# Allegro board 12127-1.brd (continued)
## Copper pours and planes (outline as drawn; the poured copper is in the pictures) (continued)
GND on TOP: 128.5,54.81 128.32,54.99 128.32,60.99 128.45,61.11 132.26,61.11 133.27,60.1 133.27,55.4 132.69,54.81 ; 2 cut-outs
GND on TOP: 118.85,151.44 118.72,151.57 118.72,153.22 118.85,153.35 120.24,153.35 120.37,153.22 120.37,151.57 120.24,151.44
GND on TOP: 186.56,178.59 186.31,178.84 185.37,178.84 185.12,179.1 185.12,180.11 185.37,180.37 185.75,180.37 186.21,179.91 186.21,179.6 186.41,179.4 188.37,179.4 188.44,179.32 188.44,178.69 188.34,178.59
GND on TOP: 180.26,173 180.16,173.1 180.16,176.35 180.21,176.4 181.89,176.4 182.27,176.78 182.27,178.08 181.28,179.07 181.28,179.86 180.16,180.97 180.16,184.63 180.26,184.73 183.85,184.73 184.28,184.3 184.28,173.35 183.92,173 ; 2 cut-outs
GND on TOP: 88.37,202.84 87,204.22 87,205.61 87.86,206.48 90.75,206.48 90.93,206.3 90.93,203.1 90.68,202.84
GND on TOP: 113.94,208.18 113.79,208.33 113.79,209.25 114,209.45 117.5,209.45 117.58,209.37 117.58,208.25 117.5,208.18
GND on BOTTOM: 14.43,3.87 14.73,4.18 14.73,5.08 12.83,6.99 12.83,8 12.06,8.76 11.43,8.76 10.79,8.13 10.79,6.86 9.73,5.79 9.73,5.21 10.39,4.55 11.48,4.55 12.15,3.87
GND on BOTTOM: 128.45,61.11 132.26,61.11 133.27,60.1 133.27,55.4 132.69,54.81 128.5,54.81 128.32,54.99 128.32,60.99
GND on BOTTOM: 154.31,80.64 154.56,80.39 154.56,76.96 152.48,74.88 137.38,74.88 136.1,76.16 136.1,80.05 136.7,80.64
GND on BOTTOM: 87.88,64.9 86.87,63.88 82.8,63.88 71.27,75.41 71.27,79.76 72.03,80.52 86.23,80.52 87.88,78.87
GND on BOTTOM: 106.68,78.61 106.68,73.79 105.66,72.77 105.66,72.39 105.92,72.14 108.08,72.14 108.33,71.88 108.33,68.96 107.95,68.58 92.48,68.58 91.44,69.62 91.44,76 94.36,78.92 106.38,78.92
GND on BOTTOM: 63.88,242.7 63.88,230.5 64.14,230.25 64.9,230.25 70.36,235.71 79.12,235.71 79.76,236.35 79.76,242.7 79.25,243.21 64.39,243.21
GND on BOTTOM: 94.92,147.63 103.86,147.63 104.11,147.38 104.11,147.32 104.78,146.66 104.78,144.91 106.17,143.51 106.99,143.51 107.41,143.09 114.62,143.09 115.92,141.79 115.92,140.65 116.18,140.39 117.7,140.39 117.83,140.52 117.83,141.79 118.08,142.04 126.34,142.04 127.35,143.06 127.35,145.83 129.03,147.51 132.18,147.51 132.56,147.12 133.58,147.12 134.34,147.89 135.19,147.89 138.23,150.93 149.45,150.93 169.54,130.84 169.54,122.46 176.04,115.97 176.04,86.96 174.71,85.64 160.39,85.64 160.1,85.34 58.93,85.34 57.66,86.61 57.66,87.76 55.89,89.52 54.85,89.52 53.63,90.74 53.63,92.85 51.69,94.79 51.69,100.66 51.66,100.69 51.66,100.97 51.03,101.6 50.29,101.6 49.91,101.22 49.91,86.49 49.78,86.36 47.77,86.36 47.65,86.49 47.65,105.05 51.44,108.84 51.44,113.7 81.81,144.08 82.52,144.08 86.6,148.15 94.4,148.15
GND on BOTTOM: outline of 119 points within 61.59,0.76 199.21,243.21
GND on BOTTOM: 15.95,236.3 16.54,235.71 19.56,235.71 19.81,235.46 19.81,229.36 15.75,225.3 10.67,225.3 10.31,225.65 10.31,228.75 9.45,229.62 9.45,232.16 9.91,232.61 14.15,232.61 14.48,232.28 14.48,227.33 14.99,226.82 15.49,226.82 17.02,228.35 17.02,234.57 16.64,234.95 15.62,234.95 14.61,233.93 3.02,233.93 0.76,231.67 0.76,242.94 0.77,242.94 0.77,243.02 0.96,243.21 15.74,243.21 15.95,243
GND on L2VCC: 31.78,6.93 40.58,6.51 31.78,6.09
GND on L2VCC: 18.62,22.42 18.22,22.81 18.22,25.7 19.89,27.37 20.91,27.37 22.42,28.88 22.42,30.02 24.45,32.05 24.45,32.81 27.24,35.61 27.24,37.51 27.38,37.66 27.73,37.66 27.88,37.51 27.88,34.5 25.34,31.96 25.34,31.07 23.43,29.16 23.43,23.95 21.89,22.42
GND on L2VCC: outline of 272 points within 0.76,0.76 199.24,243.24 ; 113 cut-outs
GND on L2VCC: 46.13,0.76 46.13,1.59 45.66,2.06 37.95,2.06 40.64,4.77 40.49,8.59 40.71,8.62 40.88,8.76 48.18,1.46 181.43,1.46 197.68,17.7 197.68,30.29 199.24,30.29 199.24,1 199.17,0.83 199,0.76 ; 1 cut-out
GND on L2VCC: 193.65,83.33 193.65,74.47
GND on L2VCC: 193.65,10.94 193.65,2.08
GND on L3: 1,0.76 0.83,0.83 0.76,1 0.76,243 0.83,243.17 1,243.24 15.88,243.24 15.88,236.24 16.53,235.59 19.45,235.59 19.81,235.23 19.81,229.59 15.64,225.43 10.13,225.43 9.14,226.42 9.14,228.17 6.93,230.38 3.66,230.38 2.92,229.64 2.92,203.22 4.47,201.68 6.96,201.68 7.49,202.21 7.49,203.22 7.73,203.45 10.65,203.45 13.59,206.4 13.59,208.3 15.22,209.93 17.12,209.93 20.93,213.74 47.07,213.74 57.86,224.54 59.16,224.54 63.75,229.13 63.75,243.24 199,243.24 199.17,243.17 199.24,243 199.24,1 199.17,0.83 199,0.76 45.72,0.76 45.62,0.86 45.62,1.91 45.19,2.34 29.03,2.34 28.78,2.08 28.78,0.92 28.63,0.76 ; 128 cut-outs
VBAT2 on L2VCC: 99.77,40.32 93.17,46.93 85.63,46.93 85.38,47.17 85.38,47.97 85.56,48.15 93.6,48.15 100.84,40.91 142.78,40.91 143.41,41.54 145.79,41.54 146.04,41.3 146.04,40.32
VCC on TOP: 187.58,21.34 184.66,24.26 184.66,27.36 186.94,29.64 190.7,29.64 191.13,29.21 191.13,21.97 190.5,21.34 ; 2 cut-outs
VCC on TOP: 170.56,51.56 170.05,52.07 170.05,54.61 170.54,55.09 173.61,55.09 174.02,54.69 174.02,52.22 173.35,51.56
VCC on TOP: 118.36,215.52 117.98,215.9 117.98,218.19 118.36,218.57 118.36,220.85 118.62,221.11 120.4,221.11 120.65,220.85 120.65,218.31 120.02,217.68 120.02,215.9 119.63,215.52 ; 2 cut-outs
VCC on TOP: 189.74,196.9 189.36,197.28 189.36,199.19 189.51,199.34 194.31,199.34 194.87,198.78 194.87,197.28 194.49,196.9
VCC on TOP: 186.79,38.68 184.47,41 181.3,41 180.31,41.99 176.56,41.99 175.87,42.67 175.87,46.51 176.1,46.74 179.15,46.74 180.34,47.93 195.78,47.93 196.09,47.62 196.09,39.12 195.66,38.68
VCC on BOTTOM: 174.37,44.07 174.37,53.34 173.99,53.72 170.31,53.72 169.42,52.83 169.42,43.81 169.93,43.31 173.61,43.31
VCC on BOTTOM: 192.53,42.8 195.83,42.8 196.47,43.43 196.47,68.58 194.31,70.74 192.02,70.74 191.64,70.36 191.64,43.69
VCC on L2VCC: 183.2,22.54 183.2,35.51 182.32,36.39 167.08,36.39 167.02,36.45 167.02,40.21 165.31,41.92 161.29,41.92 155.99,47.22 155.99,49.43 156.92,50.36 166.61,50.36 166.7,50.37 166.77,50.42 171.55,55.16 177.7,55.16 178.63,56.08 178.63,65.25 179.15,65.77 183.21,65.77 183.83,66.39 183.83,87.04 189.93,93.14 189.93,108.38 191.2,109.65 191.2,116 193.36,118.16 193.36,186.01 191.45,187.91 191.45,196.17 190.58,197.04 190.56,197.04 190.56,200.47 199.24,200.47 199.24,30.67 191.95,30.67 190.44,29.16 190.44,23.45 189.53,22.54 ; 1 cut-out
VCC3 on TOP: 10.16,37.72 9.02,38.86 9.02,41.4 9.14,41.53 9.53,41.53 9.78,41.27 9.78,40.01 9.91,39.88 13.08,39.88 13.34,39.62 13.34,39.24 13.08,38.99 11.43,38.99 11.18,38.73 11.18,37.85 11.05,37.72 ; 2 cut-outs
VCC3 on TOP: outline of 128 points within 12.42,51.41 31.11,67.06 ; 11 cut-outs
VCC3 on TOP: 20.14,188.21 18.97,189.38 17.58,189.38 17.37,189.59 17.37,191.29 17.65,191.57 19.33,191.57 20.14,190.75 20.9,190.75 24.08,193.93 24.08,193.94 24.9,194.76 29.09,194.76 30.86,192.99 32.92,192.99 33.46,192.44 35.75,192.44 35.89,192.3 36.14,192.3 36.3,192.15 38.4,192.15 38.79,191.77 39.75,191.77 40.64,190.88 43.05,190.88 43.31,190.63 43.31,188.85 42.93,188.47 40.64,188.47 39.5,189.61 38.25,189.61 38.24,189.62 37.88,189.62 36.45,191.06 33.3,191.06 31.6,189.36 26.67,189.36 26.65,189.38 25.76,189.38 25.02,188.63 21.83,188.63 21.41,188.21 ; 8 cut-outs
VCC3 on TOP: 100.08,37.74 99.75,38.07 99.75,41.53 105.59,47.37 105.59,51 105.38,51.21 102.51,51.21 101.96,51.77 98.15,51.77 98.06,51.85 98.06,52.31 98.12,52.37 102.23,52.37 102.59,52.02 103.07,52.02 103.43,52.37 106.38,52.37 106.88,51.87 106.88,46.79 101.09,41 101.09,38.02 100.81,37.74 ; 2 cut-outs
VCC3 on TOP: 47.9,22.53 46.99,23.44 47.02,23.44 47.02,24.74 47.07,24.79 47.96,24.79 48.9,23.85 50.04,23.85 50.29,23.6 50.29,22.73 50.09,22.53
VCC3 on TOP: 69.24,73 68.12,74.12 61.09,74.12 60.96,74.24 60.96,75.26 61.21,75.51 70.18,75.51 70.51,75.18 70.51,73.25 70.26,73
VCC3 on TOP: 110.24,8.51 110.11,8.64 110.11,11.68 110.24,11.81 110.87,11.81 111.12,12.06 111.63,12.06 111.89,11.81 111.89,9.02 111.38,8.51 ; 1 cut-out
VCC3 on TOP: 55.37,85.09 53.72,86.74 53.72,87.38 53.98,87.63 53.98,89.66 54.74,90.42 54.74,91.19 53.72,92.2 53.72,93.47 54.74,94.49 54.74,95.38 54.23,95.89 54.23,96.77 54.61,97.16 55.5,97.16 57.28,95.38 57.28,90.55 57.66,90.17 57.66,85.47 57.28,85.09
VCC3 on TOP: 15.8,233.17 15.16,233.81 14.1,233.81 13.94,233.96 13.94,235.59 13.59,235.94 13.59,236.58 13.79,236.78 16,236.78 16.84,235.94 17.68,235.94 17.86,235.76 17.86,233.43 17.6,233.17 ; 1 cut-out
VCC3 on TOP: 15.01,40.01 14.33,40.69 14.33,41.83 13.74,42.42 13.74,44.04 11.73,46.05 11.73,47.19 11.81,47.27 12.17,47.27 12.73,47.83 13.41,47.83 13.94,48.36 15.8,48.36 15.88,48.29 15.88,47.83 15.7,47.65 14.22,47.65 14.07,47.5 14.07,44.58 14.55,44.09 15.75,44.09 15.85,43.99 15.85,42.75 15.49,42.39 15.49,40.77 15.34,40.61 15.34,40.13 15.21,40.01 ; 5 cut-outs
VCC3 on TOP: 182.25,59.31 181.23,60.33 181.23,67.56 182.25,68.58 194.82,68.58 195.83,67.56 195.83,60.33 194.82,59.31 ; 2 cut-outs
VCC3 on TOP: 75.82,59.44 74.17,61.09 63.73,61.09 63.22,61.59 63.22,66.34 63.3,66.42 65.91,66.42 66.04,66.29 66.04,63.37 66.29,63.12 76.58,63.12 77.47,62.23 77.47,61.47 78.74,60.2 78.74,59.69 78.49,59.44 ; 4 cut-outs
VCC3 on BOTTOM: 79.2,57.73 79.2,46.43 79.18,46.42 79.18,45.66 78.49,44.96 77.22,44.96 76.48,45.69 76.48,66.4 69.27,73.61 69.27,75.49 69.41,75.63 70.04,75.63 81.15,64.52 81.15,59.69
VCC3 on BOTTOM: 54.86,80.52 54.86,85.47 55.37,85.98 57.28,85.98 57.53,85.72 57.53,82.93 59.31,81.15 60.83,81.15 63.37,78.61 63.37,75.18 62.48,74.3 61.09,74.3
VCC3 on BOTTOM: 186.69,45.47 185.93,44.7 185.93,28.96 184.91,27.94 184.91,23.75 185.8,22.86 195.58,22.86 196.34,22.1 196.34,17.02 195.2,15.88 181.36,15.88 176.96,20.27 176.96,30.38 177.1,30.52 177.1,40.09 178.71,41.71 178.71,46.2 180.59,48.08 180.59,62.31 186.99,68.71 190.02,68.71 190.37,68.35 190.37,59.69 189.99,59.31 187.83,59.31 186.69,58.17
VCC3 on L2VCC: outline of 143 points within 6.54,13.4 182.82,197.68 ; 1 cut-out
VCC3_3SBREF on TOP: 173.99,20.19 173.48,20.7 173.48,23.24 173.74,23.5 177.16,23.5 177.29,23.37 177.29,21.21 177.04,20.95 176.4,20.95 175.64,20.19 ; 4 cut-outs
VCC12CPU on TOP: 180.85,188.67 179.15,190.37 175.64,190.37 175.43,190.16 175.09,190.16 175.09,189.83 174.62,189.36 156.72,189.36 143.76,202.31 135.59,202.31 134.32,203.58 130.89,203.58 129.95,202.64 112.22,202.64 111,201.42 106.93,201.42 106.24,200.72 106.23,200.72 106.05,200.53 93.6,200.53 91.54,202.59 91.54,207.31 91.67,207.44 106.88,207.44 108.32,208.88 112.46,208.88 113.77,207.57 117.75,207.57 117.96,207.77 117.96,208.77 118.07,208.88 126.78,208.88 127.24,209.34 146.63,209.35 159.38,196.6 179.16,196.6 179.16,196.55 180.16,195.62 181.16,196.55 181.17,196.6 189.61,196.6 194.61,196.6 195.3,196.6 195.73,196.17 195.73,190.98 195.1,190.36 186.42,190.36 184.73,188.67 ; 2 cut-outs
VCC12CPU on BOTTOM: 185.47,194.77 185.9,195.2 190.27,195.2 191.01,194.46 191.01,190.86 190.63,190.47 186.51,190.47 185.47,191.52
VCC12CPU on L2VCC: 187.28,188.02 184.99,190.31 175.56,190.31 174.67,189.42 156.67,189.42 143.97,202.12 135.71,202.12 134.32,203.52 130.48,203.52 129.46,202.5 118.57,202.5 118.32,202.76 112.32,202.76 110.92,201.36 106.98,201.36 106.09,200.47 100.76,200.47 100.27,199.98 100.27,198.58 100,198.31 98.25,198.31 97.98,198.58 97.98,199.98 97.49,200.47 93.8,200.47 91.38,202.9 91.38,207.26 91.68,207.56 107,207.56 108.32,208.88 126.78,208.88 127.26,209.36 146.86,209.36 159.56,196.66 190.42,196.66 191.07,196.01 191.07,188.29 190.8,188.02
1P5V_AUX on TOP: 111.51,64.9 109.22,67.18 109.22,69.05 109.24,69.07 109.24,78.76 109.91,79.43 126.62,79.43 126.87,79.17 126.87,72.82 123.83,69.77 123.83,66.6 123.27,66.04 122.68,66.04 121.54,64.9 ; 2 cut-outs
1P5V_AUX on BOTTOM: 124.33,76.58 126.87,74.04 126.87,72.82 123.83,69.77 123.83,66.6 123.27,66.04 122.68,66.04 121.54,64.9 111.51,64.9 109.22,67.18 109.22,75.82 109.98,76.58
1P5V_AUX on L2VCC: 113.21,63.08 110.43,65.86 110.43,67.87 118.94,76.38 118.94,78.79 119.84,79.69 126.4,79.69 126.94,79.05 126.94,63.32 126.69,63.08
AUD_AVDD on TOP: 27.23,224.66 26.38,225.51 26.38,226.3 25.6,227.08 24.89,227.08 24.69,227.28 24.69,227.74 24.79,227.84 26.47,227.84 28.07,226.24 29.08,226.24 29.36,225.96 29.36,224.79 29.24,224.66
AUD_AVDD on TOP: 23.37,235.84 22.07,237.13 22.02,237.13 21.79,237.36 21.79,237.87 21.92,238 22.4,238 22.58,237.82 24.23,237.82 24.38,237.67 24.38,235.97 24.26,235.84 ; 3 cut-outs
AUD_AVDD on BOTTOM: 24.51,231.32 27.81,228.02 27.81,227.08 27.18,226.44 26.34,226.44 22.76,230.02 22.76,236.07 21.72,237.11 21.72,237.74 21.97,238 24.38,238 24.51,237.87
LAN_1P05_OUT on TOP: 159.38,200.66 158.88,201.17 158.88,201.93 159.13,202.18 159.89,202.18 160.15,201.93 160.15,201.68 160.27,201.55 162.56,201.55 162.81,201.8 162.81,205.1 162.94,205.23 165.86,205.23 166.04,205.41 168.25,205.41 168.28,205.38 168.28,204.44 167.87,204.04 166.57,204.04 165.89,203.35 165.89,202.13 165.74,201.98 165.15,201.98 163.83,200.66 ; 2 cut-outs
MEM_LX on TOP: 117.78,55.14 117.68,55.24 117.68,56.95 117.45,57.18 116.18,57.18 115.49,56.49 114.76,56.49 114.68,56.57 114.68,57.15 114.43,57.4 111.86,57.4 111.4,57.86 111.4,60.86 113.23,62.69 127.64,62.69 127.81,62.51 127.81,57.53 127.69,57.4 125.04,57.4 124.36,56.72 124.36,55.27 124.23,55.14 ; 1 cut-out
MEM_LX on BOTTOM: 127.64,62.69 127.81,62.51 127.81,55.55 127.41,55.14 112.19,55.14 111.4,55.93 111.4,60.86 113.23,62.69
MEM_LX on L2VCC: 112.19,55.13 111.39,55.93 111.39,60.87 113.22,62.7 127.1,62.7 127.13,62.7 127.45,62.7 127.95,62.2 127.95,55.68 127.4,55.13
MEM_VIN on TOP: 119.3,33.32 109.75,42.88 109.75,46.38 111.18,47.8 112.73,47.8 113.77,48.84 113.77,52.15 116.43,54.81 121.41,54.81 121.54,54.69 121.54,49.16 123.85,46.85 123.85,40.44 126.87,37.41 126.87,34.26 125.93,33.32
MEM_VIN on BOTTOM: 126.8,37.16 120.73,37.16 120.35,36.78 120.35,34.21 123.7,30.86 126.67,30.86 127.13,31.32 127.13,36.83
MEM_VIN on BOTTOM: 109.63,48.72 109.63,43.41 110.03,43 123.44,43 123.93,43.48 123.93,49.15 123.24,49.83 110.74,49.83
PWM1_LX on TOP: 175.11,172.69 175.1,172.7 174.41,172.7 174.37,172.74 174.37,173.43 161.75,186.06 161.75,188.57 162,188.82 166.57,188.82 166.67,188.72 166.67,187.1 166.83,186.94 169.14,186.94 169.49,187.3 169.49,188.62 169.72,188.85 172.97,188.85 173.1,188.72 173.1,187.07 173.35,186.82 173.89,186.82 174.42,186.28 179.43,186.28 179.65,186.06 179.65,181.05 179.45,180.85 177.12,180.85 176.81,180.53 176.81,180.53 176.6,180.32 176.6,178.63 177.13,178.11 179.65,178.11 179.78,177.98 179.78,172.85 179.63,172.69
PWM1_LX on BOTTOM: 179.78,177.93 179.78,174.45 179.32,173.99 173.86,173.99 172.97,174.88 172.97,178.61 171.28,180.3 170.81,180.3 170.81,180.31 170.46,180.31 169.29,181.48 168.91,181.48 168.61,181.18 168.61,180.42 168.4,180.21 167.64,180.21 162,185.85 162,186.59 162.46,187.05 174.27,187.05 175.06,186.26 179.4,186.26 179.65,186 179.65,181.05 179.45,180.85 178.18,180.85 177.55,180.21 177.55,178.69 177.93,178.31 179.4,178.31
PWM1_LX on L2VCC: 174.96,172.66 161.48,186.13 161.48,189.04 173.04,189.04 173.04,187.37 173.53,186.88 179.25,186.88 179.77,186.36 179.77,181.05 179.55,180.84 177.12,180.84 176.61,180.33 176.61,178.63 177.12,178.11 179.63,178.11 179.77,177.98 179.77,173.05 179.37,172.66
PWM2_LX on TOP: 129.41,185.8 118.49,196.72 118.49,202.06 118.75,202.31 121.92,202.31 122.05,202.18 122.05,200.41 122.3,200.15 124.71,200.15 124.97,200.41 124.97,202.18 125.09,202.31 128.14,202.31 128.27,202.18 128.27,200.15 128.65,199.77 134.37,199.77 134.62,199.52 134.62,194.44 134.49,194.31 132.97,194.31 132.59,193.93 132.59,191.64 132.97,191.26 134.49,191.26 134.62,191.13 134.62,185.93 134.49,185.8
PWM2_LX on BOTTOM: 128.17,200.28 128.66,199.78 134.35,199.78 134.62,199.52 134.62,194.44 134.49,194.31 132.97,194.31 132.59,193.93 132.59,191.64 132.97,191.26 134.49,191.26 134.62,191.13 134.62,185.93 134.49,185.8 129.92,185.8 121.28,194.44 121.28,196.72 118.64,199.36 118.64,200.05 118.87,200.28
PWM2_LX on L2VCC: 129.62,185.86 118.68,196.8 118.68,202.11 118.7,202.12 128.06,202.12 128.08,202.11 128.08,200.07 128.57,199.58 134.29,199.58 134.43,199.44 134.43,194.52 134.29,194.37 133.14,194.37 132.65,193.88 132.65,191.82 133.14,191.33 134.29,191.33 134.56,191.06 134.56,186.13 134.29,185.86
PWM3_LX on TOP: 93.85,183.36 93.73,183.49 93.73,188.57 94.11,188.95 95.76,188.95 96.01,189.2 96.01,191.36 95.76,191.62 93.98,191.62 93.85,191.74 93.85,197.1 92.71,198.25 88.82,198.25 88.7,198.37 88.7,198.96 88.87,199.14 91.54,199.14 92.43,200.03 97.54,200.03 97.66,199.9 97.66,198.3 97.97,197.99 100.41,197.99 100.58,198.17 100.58,199.75 100.86,200.03 103.63,200.03 103.89,199.77 103.89,198.09 106.1,195.88 106.1,192.07 101.63,187.6 101.63,186.31 98.68,183.36
PWM3_LX on BOTTOM: 93.73,183.9 93.73,188.57 94.09,188.94 95.77,188.94 96.01,189.18 96.01,191.34 95.76,191.59 94.11,191.59 93.85,191.85 93.85,197.82 93.88,197.84 93.88,198.12 94.26,198.5 97.52,198.5 98.04,197.98 104.01,197.98 105.79,196.2 105.79,193.29 105.66,193.17 105.41,193.17 105.16,193.42 104.9,193.42 104.39,192.91 104.39,192.66 105.16,191.9 105.16,191.08 101.62,187.54 101.62,186.31 98.81,183.51 98.81,183.51 94.11,183.51
PWM3_LX on L2VCC: 94.06,183.58 93.66,183.97 93.66,188.52 94.06,188.91 95.33,188.91 95.95,189.53 95.95,191.21 95.58,191.58 94.19,191.58 93.79,191.98 93.79,200.09 97.33,200.09 97.6,199.82 97.6,198.42 98.09,197.93 100.15,197.93 100.65,198.42 100.65,199.82 100.92,200.09 103.68,200.09 103.95,199.82 103.95,197.79 105.85,195.88 105.85,192.1 101.54,187.78 101.54,186.39 98.73,183.58
SB3V on TOP: 6.71,47.27 4.45,49.53 4.45,51.05 4.19,51.31 4.19,52.83 4.57,53.21 5.71,53.21 5.97,52.96 5.97,51.56 8.23,49.3 8.23,47.9 7.59,47.27
SB3V on TOP: 8.97,103.15 8.76,103.35 8.76,104.09 8.99,104.32 8.99,105.99 6.12,108.86 6.12,110.41 7.09,111.38 9.68,111.38 9.78,111.28 9.78,110.46 9.14,109.83 9.14,108.79 9.3,108.64 9.3,107.67 10.31,106.65 10.31,103.4 10.06,103.15 ; 7 cut-outs
SB3V on TOP: 191.77,203.84 191.52,204.09 191.52,205.49 191.77,205.74 194.06,205.74 194.31,205.49 194.31,204.09 194.06,203.84
SB3V on TOP: 13.08,29.46 12.95,29.59 12.95,31.88 13.21,32.13 14.35,32.13 14.61,31.88 14.61,29.59 14.48,29.46 ; 7 cut-outs
SB3V on TOP: 193.6,222.5 193.47,222.63 193.47,223.27 193.57,223.37 194.08,223.37 194.34,223.62 194.34,224.74 193.27,225.81 192.63,225.81 191.36,224.54 190.7,224.54 190.55,224.38 190.55,223.95 190.37,223.77 189.48,223.77 189.23,224.03 189.23,225.91 189.41,226.09 190.02,226.09 191.21,227.28 193.9,227.28 195.86,225.32 195.86,222.94 195.43,222.5 ; 3 cut-outs
SB3V on TOP: 163.96,18.8 163.7,19.05 163.7,20.19 164.85,21.34 167.39,21.34 168.4,20.32 168.4,19.05 168.28,18.92 165.1,18.92 164.97,18.8
SB3V on TOP: 27.32,24.73 27.19,24.85 27.19,26.43 27.28,26.52 28.14,26.52 28.18,26.48 28.18,24.83 28.08,24.73
SB3V on BOTTOM: 191.52,203.84 185.29,210.06 185.29,214.12 193.45,222.28 193.45,224.08 193.68,224.31 194.97,224.31 195.22,224.05 195.22,221.64 186.82,213.23 186.82,210.31 191.39,205.74 194.06,205.74 194.31,205.49 194.31,204.09 194.06,203.84
SB3V on BOTTOM: 164.72,20.83 164.72,9.78 165.1,9.4 167.89,9.4 168.28,9.78 168.28,20.45 167.26,21.46 165.35,21.46
SB3V on L2VCC: 81.36,6.92 76.15,12.13 44.4,12.13 40.34,16.19 32.94,16.19 26.34,9.59 12.78,9.59 10.26,12.1 8.72,12.1 8.45,12.39 8.45,34.75 6.54,36.65 6.54,49.97 9.83,49.97 11.62,48.18 11.62,45.77 13.13,44.26 14.05,44.26 14.41,44.63 14.41,47.04 14.56,47.18 16.94,47.18 18.59,45.53 20.37,45.53 21.78,44.12 21.78,38.31 19.86,36.39 19.23,36.39 11.87,29.03 11.87,19.61 14.15,17.34 29.29,17.34 30.3,18.35 41.83,18.35 45.01,15.18 79.02,15.18 82.39,11.8 91.7,11.8 95.33,15.43 104.95,15.43 107.36,13.02 112.57,13.02 114.86,10.73 157.56,10.73 158.18,11.35 158.18,13.02 168.34,13.02 168.34,8.08 167.18,6.92
SB5V on TOP: 156.08,17.53 155.7,17.91 155.7,22.99 155.96,23.24 158.24,23.24 158.5,22.99 158.5,17.91 158.12,17.53
SB5V on BOTTOM: 156.84,21.46 156.59,21.21 153.16,21.21 132.72,0.76 28.83,0.76 28.7,0.89 28.7,1.52 29.08,1.91 115.87,1.91 116.55,2.58 132.37,2.58 152.91,23.11 156.59,23.11 156.84,22.86
SB5V on L2VCC: 28.73,0.76 28.73,1.59 29.65,2.51 32.32,2.51 33.08,1.75 35.57,1.75 36.17,1.71 36.77,1.75 45.53,1.75 45.82,1.46 45.82,0.76
SB5V on L3: 29.29,0.76 29.06,0.99 29.06,1.88 29.31,2.13 45.19,2.13 45.42,1.91 45.42,0.91 45.26,0.76
USBVCC01 on TOP: 138.3,215.9 136.91,217.3 136.91,221.74 140.21,225.04 141.73,225.04 142.24,224.54 142.24,217.68 141.78,217.22 141.78,213.16 141.6,212.98 138.43,212.98 138.3,213.11 ; 6 cut-outs
USBVCC01 on BOTTOM: 142.62,223.27 142.11,222.76 135.38,222.76 134.56,223.58 134.56,234.12 135.13,234.7 137.16,234.7 142.62,229.24
USBVCC23 on TOP: 148.34,213.23 147.96,213.61 147.96,216.92 148.72,217.68 151.51,217.68 152.27,218.44 152.27,219.58 151.89,219.96 151.89,226.89 153.35,228.35 153.35,229.17 153.29,229.24 153.29,230.63 152.65,231.27 152.65,232.92 153.54,233.81 155.32,233.81 156.08,233.04 157.73,233.04 160.27,230.5 160.27,227.08 158.12,224.92 158.12,219.2 152.15,213.23 ; 6 cut-outs
USBVCC45 on TOP: 166.85,71.73 166.45,72.14 166.45,79.76 166.7,80.01 170.71,80.01 170.89,79.83 170.89,75.54 171.32,75.11 175.39,75.11 175.67,74.83 175.67,74.24 175.51,74.09 175.51,72.8 175.41,72.69 174.83,72.69 174.78,72.75 174.78,73.76 174.5,74.04 173.58,74.04 172.95,73.41 170.74,73.41 170.71,73.38 170.43,73.38 170.23,73.18 170.23,71.98 169.98,71.73 ; 4 cut-outs
USBVCC89 on TOP: 186.11,228.5 185.98,228.63 185.98,232.87 184.99,233.86 182.85,233.86 182.22,234.49 182.22,237.19 182.37,237.34 183.41,237.34 184.02,237.95 189.33,237.95 190.75,236.52 190.75,232.74 189.41,231.39 189.41,228.8 189.15,228.55 188.54,228.55 188.24,228.24 187.4,228.24 187.15,228.5 ; 3 cut-outs
USBVCC89 on BOTTOM: 184.51,226.95 172.97,226.95 172.09,227.84 172.09,235.46 173.79,237.16 176.91,237.16 178.96,235.12 181.32,235.12 184,237.79 186.18,237.79 187.16,236.82 187.16,229.6
USBVCC1011 on TOP: 129.51,73.99 129.51,78.97 134.04,83.49 158.17,83.49 164.13,77.52 164.13,69.24 163.86,68.96 161.77,68.96 161.21,69.52 161.21,77.29 157.1,81.41 144.27,81.41 142.37,79.5 142.37,64.95 145.72,61.59 147.73,61.59 148.03,61.29 148.03,57.58 147.52,57.07 145.77,57.07 145.01,56.31 138.71,56.31 137.03,57.99 137.03,66.47 ; 2 cut-outs
USBVCC1011 on BOTTOM: 150.98,68.17 152.68,68.17 153.21,68.71 159.89,68.71 160.63,69.44 160.63,73.48 161.44,74.3 162.61,74.3 163.32,73.58 163.32,64.52 162.28,63.47 159.94,63.47 157.18,66.24 150.9,66.24 150.6,66.55 150.6,67.79
V_1P5_DAC_FB_R on TOP: 24.77,67.18 24.64,67.31 24.64,68.45 23.75,69.34 23.75,70.74 24,70.99 25.53,70.99 25.78,70.74 25.78,67.31 25.65,67.18 ; 4 cut-outs
V_1P05_LAN on TOP: 160.78,201.93 160.02,202.69 159.13,202.69 158.12,203.71 158.12,205.49 158.37,205.74 160.27,205.74 160.66,205.36 162.05,205.36 162.43,204.98 162.43,202.18 162.18,201.93 ; 4 cut-outs
V_1P05_LAN on BOTTOM: 173.23,208.79 172.95,209.07 168.11,209.07 167.2,208.15 165.61,208.15 162.43,204.98 158.37,204.98 157.99,204.6 157.99,201.8 158.37,201.42 164.34,201.42 165.76,202.84 171.81,202.84 173.23,204.27
V_1P5_PCH on TOP: 57.25,62.08 56.87,62.46 56.87,64.62 56.92,64.67 60.91,64.67 61.24,64.34 62.74,64.34 62.81,64.27 62.81,62.3 62.59,62.08 ; 13 cut-outs
V_1P05_PCH on TOP: 57.02,33.43 56.9,33.55 56.9,36.58 55.88,37.59 55.88,39.24 56.13,39.5 58.7,39.5 59.18,39.98 60.43,39.98 61.21,40.77 65.28,40.77 65.53,40.51 65.53,37.59 66.19,36.93 66.19,34.42 65.2,33.43 ; 12 cut-outs
V_1P5_PCH on TOP: 45.82,35.79 44.3,37.31 44.3,37.72 44.48,37.9 44.48,38.33 44.3,38.51 44.3,38.71 44.42,38.84 44.55,38.84 46.84,36.55 46.84,36.04 46.58,35.79
V_1P05_PCH on BOTTOM: 33.88,51.54 37.57,51.54 38.58,50.52 38.58,50.14 37.95,49.5 37.95,46.71 37.56,46.33 37.56,44.42 37.34,44.2 33.66,44.2 31.62,46.23 31.62,50.67 32.49,51.54
V_1P5_PCH on BOTTOM: 57.91,64.26 58.09,64.08 58.09,62.23 57.94,62.08 57.18,62.08 56.87,61.77 56.87,55.63 56.67,55.42 56.67,53.92 54.97,52.22 52.1,52.22 51.56,51.69 51.03,51.69 50.72,51.99 50.72,52.17 51.77,53.21 51.79,53.21 52.12,53.54 54.53,53.54 55.73,54.74 55.73,55.27 55.12,55.88 55.12,59.69 49.66,65.15 49.66,66.27 50.01,66.62 51.03,66.62 53.39,64.26
V_1P05_PCH on L2VCC: 48.97,25.21 48.72,25.46 45.54,25.46 44.66,26.35 39.45,26.35 36.78,29.02 35.51,29.02 34.48,30.05 34.48,31.83 31.81,34.5 31.81,50.47 32.59,51.24 38.15,51.24 38.42,50.98 38.42,42.85 40.45,40.82 40.45,38.53 41.07,37.91 44.88,37.91 45.51,37.27 50.88,37.27 53.04,39.43 59.26,39.43 61.04,41.21 76.01,41.21 76.01,34.62 74.09,32.7 65.33,32.7 57.83,25.21
V_1P05V on TOP: 61.72,41.53 61.47,41.78 61.47,42.67 60.71,43.43 59.31,43.43 58.42,44.32 58.42,46.48 59.18,47.24 64.14,47.24 66.04,45.34 69.85,45.34 70.1,45.09 70.1,43.69 68.96,42.55 68.96,41.78 68.71,41.53 ; 4 cut-outs
V_3P3_A on TOP: 160.27,6.6 155.57,11.3 155.57,12.45 156.08,12.95 157.35,12.95 157.63,12.67 163.53,12.67 163.88,12.32 163.88,9.55 164.92,8.51 179.96,8.51 180.97,9.53 180.97,10.54 180.47,11.05 165.61,11.05 165.1,11.56 165.1,17.78 165.61,18.29 168.53,18.29 168.91,18.67 177.04,18.67 179.32,16.38 182.88,16.38 183.9,15.37 183.9,8.89 181.61,6.6
V_3P3_A on TOP: 18.92,31.5 18.8,31.62 18.8,32.26 18.92,32.38 19.81,32.38 20.45,33.02 20.45,34.04 20.57,34.16 21.21,34.16 21.72,34.67 21.72,35.41 23.75,37.44 24.05,37.44 24.13,37.36 24.13,36.86 23.21,35.94 22.99,35.71 22.99,33.27 22.1,32.38 21.46,32.38 20.57,31.5 ; 1 cut-out
V_3P3_A on L2VCC: 115.01,11.11 112.73,13.4 107.52,13.4 105.11,15.81 95.17,15.81 91.54,12.18 82.55,12.18 79.17,15.56 45.16,15.56 41.99,18.73 30.15,18.73 29.13,17.72 14.3,17.72 12.26,19.76 12.26,28.88 19.38,36 20.02,36 22.05,38.04 24.56,38.04 24.96,37.64 24.96,37.04 24.69,36.77 23.92,36.77 22.54,35.38 22.54,33.86 19.86,31.18 17.45,31.18 14.67,28.4 14.67,21.26 15.92,20 29.03,20 29.54,20.51 42.97,20.51 46.02,17.46 80.31,17.46 83.26,14.52 89.97,14.52 93.8,18.35 108.13,18.35 110.41,16.07 112.95,16.07 116,13.02 157.8,13.02 157.8,11.51 157.4,11.11
V_3P3_LAN on TOP: 174.12,203.3 173.23,204.19 171.32,204.19 171.2,204.32 171.2,204.95 171.32,205.08 171.7,205.08 171.83,204.95 173.86,204.95 174.62,204.19 175.26,204.19 175.39,204.32 175.64,204.32 175.9,204.06 175.9,203.56 175.64,203.3 ; 2 cut-outs
V_3P3_LAN on TOP: 181.61,220.09 181.1,220.6 181.1,221.23 181.86,222 184.4,222 187.07,224.66 187.07,225.68 187.58,226.19 188.59,226.19 188.72,226.06 188.72,222.88 188.09,222.25 186.46,222.25 185.65,221.44 185.65,220.78 185.5,220.62 183.92,220.62 183.39,220.09 ; 6 cut-outs
V_3P3_LAN on TOP: 166.45,214.58 165.94,215.09 165.07,215.09 164.16,216 164.16,220.04 164.67,220.55 169.09,220.55 169.49,220.14 169.49,218.92 169.14,218.57 167.44,218.57 167.06,218.19 167.06,214.66 166.98,214.58 ; 3 cut-outs
V_3P3_LAN_VDDSREG on TOP: 165.74,205.64 165.63,205.74 162.94,205.74 162.81,205.87 162.81,206.63 162.94,206.76 163.83,206.76 163.96,206.63 165.99,206.63 166.8,205.82 168.25,205.82 168.28,205.79 168.28,205.66 168.25,205.64
V_3P3_PCIVAUX on TOP: 41.02,143.38 40.89,143.51 40.89,144.4 41.02,144.53 43.81,144.53 43.94,144.65 46.35,144.65 46.74,145.03 46.74,159.51 45.21,161.04 45.21,167.13 44.96,167.39 43.94,167.39 43.81,167.51 43.81,168.02 43.94,168.15 44.96,168.15 45.21,168.4 45.21,170.41 42.72,172.9 41.35,172.9 39.62,174.62 36.78,174.62 34.87,176.53 34.87,178.69 35.08,178.89 36.07,178.89 36.25,178.71 36.25,177.52 37.16,176.61 38.35,176.61 39.09,177.34 39.09,178.26 39.32,178.49 39.78,178.49 42.75,175.51 43.94,175.51 48.13,171.32 48.13,144.65 46.99,143.51 44.2,143.51 44.07,143.38 ; 2 cut-outs
V_3P3_PCIVAUX on TOP: 5.69,111.79 5.69,113.08 5.73,113.12 5.73,116.33 6.6,117.21 6.6,168.68 2.16,173.13 2.16,188.47 4.18,190.49 12.69,190.49 13,190.8 15.06,190.8 15.27,190.6 15.27,189.36 13.48,187.57 6.09,187.57 4.7,186.18 4.7,174.9 9.6,170 9.6,112.01 9.37,111.79 ; 8 cut-outs
V_3P3_PCIVAUX on TOP: 22.1,186.18 21.67,186.61 21.67,187.76 22.15,188.24 30.96,188.24 33.43,190.7 35.13,190.7 35.69,190.14 35.69,189 34.59,187.91 34.16,187.91 32.72,186.46 32.18,186.46 31.9,186.18 ; 2 cut-outs
V_3P3_PCIVAUX on BOTTOM: 12.84,190.36 13.18,190.7 13.21,190.7 13.51,191.01 14.61,191.01 15.49,191.9 19.43,191.9 20.57,190.75 21.21,190.75 22.38,189.59 22.38,189.53 23.06,188.85 23.06,186.77 21.97,185.67 21.97,182.88 20.19,181.1 14.73,181.1 12.84,182.99
V_3P3_PCIVAUX on BOTTOM: 43,185.98 42.99,185.97 42.99,181.75 40.64,179.4 40.64,178.36 39.62,177.34 36.07,177.34 33.34,180.07 33.34,181.01 33.2,181.15 33.2,181.61 33.11,181.7 33.11,182.87 32.89,183.08 32.89,189.99 33.78,190.88 35.31,190.88 36.09,190.09 39.57,190.09 40.82,188.85 42.32,188.85 43,188.16
V_5_CODEC on TOP: 16.69,236.47 16.41,236.75 16.41,241.07 17.4,242.06 26.42,242.06 27.71,240.77 27.71,239.17 27.58,239.04 26.95,239.04 26.77,238.86 26.77,236.83 26.52,236.58 25.12,236.58 24.79,236.91 24.79,239.37 24.26,239.9 19.68,239.9 19.11,239.33 19.11,237.3 18.29,236.47 ; 3 cut-outs
V_5_CODEC on BOTTOM: 24.99,239.98 26.75,239.98 27.25,239.47 27.25,236.63 26.57,235.94 26.57,233.15 29.46,230.25 29.46,229.06 29.24,228.83 27.74,228.83 24.87,231.7 24.87,239.85
V_5P0_A on TOP: 171.6,56.77 171.5,56.87 171.5,57.63 171.58,57.71 175.01,57.71 175.18,57.53 175.18,56.92 175.03,56.77
V_5P0_A on TOP: 189.48,200.99 189.33,201.14 189.33,201.9 189.48,202.06 194.64,202.06 194.84,201.85 194.84,201.35 194.49,200.99
V_5P0_A on TOP: 159.38,18.41 159.07,18.73 159.07,25.01 159.79,25.73 166.73,25.73 166.74,25.74 168.34,25.74 172.25,29.65 174.03,29.65 174.7,30.33 175.49,30.33 175.69,30.12 175.69,29.34 176.07,28.96 180.21,28.96 183.26,32 183.26,32.92 185.65,35.31 195.33,35.31 195.83,34.8 195.83,30.96 195.17,30.3 187.22,30.3 183.44,26.52 183.44,25.96 182.4,24.92 177.04,24.92 177.03,24.93 173.99,24.93 173.15,24.09 173.15,21.03 172.31,20.19 169.42,20.19 167.64,21.97 164.47,21.97 163.07,20.57 163.07,18.8 162.69,18.41 ; 10 cut-outs
V_5P0_A on BOTTOM: 187.07,30.35 195.33,30.35 195.83,30.86 195.83,34.8 195.33,35.31 187.07,35.31 186.44,34.67 186.44,30.99
V_5P0_HDMI_CONN on TOP: 117.47,227.46 115.82,229.11 115.82,235.33 115.7,235.46 115.44,235.46 115.32,235.33 115.06,235.33 114.81,235.59 114.81,235.97 115.19,236.35 116.2,236.35 116.97,235.59 116.97,231.39 119.89,228.47 119.89,227.71 119.63,227.46 ; 2 cut-outs
V_CPU_CORE on TOP: 105.46,149.84 104.88,150.42 104.88,153.86 103.48,155.25 103.22,155.25 102.72,155.76 102.72,155.89 102.97,156.14 103.1,156.14 103.35,155.89 103.73,155.89 103.86,156.01 103.86,156.27 102.84,157.28 102.84,157.79 102.97,157.92 103.22,157.92 104.37,156.78 106.15,156.78 107.29,157.92 107.67,157.92 108.18,157.41 108.69,157.41 109.19,157.92 109.19,158.81 109.5,159.11 112.29,159.11 112.9,159.72 113.21,159.72 113.71,159.21 114.3,159.21 114.78,159.7 114.78,160.71 115.29,161.22 115.29,162.49 115.59,162.8 115.97,162.8 116.56,163.38 116.94,163.38 117.45,163.89 117.45,164.32 118.01,164.88 118.01,165.31 117.45,165.87 117.45,166.2 117.7,166.45 117.88,166.45 117.96,166.53 117.96,167.19 117.45,167.7 117.45,168.59 105.06,180.97 103.15,180.97 102.97,181.15 102.97,187.43 109.09,193.55 120.45,193.55 129.08,184.91 132.45,184.91 132.45,184.91 133.23,184.91 134.62,183.51 162.81,183.51 167.64,178.69 167.64,172.47 166.29,171.13 139.67,171.13 136.88,168.33 131,168.33 130.02,167.36 130.02,158.43 127.1,155.51 127.1,154.18 126.87,153.95 126.87,153.16 127.1,152.93 127.1,150.63 126.31,149.84
V_CPU_CORE on BOTTOM: 129.39,184.72 133.48,184.72 134.68,183.51 162.81,183.51 167.64,178.69 167.64,173.74 164.97,171.07 139.57,171.07 136.91,168.4 130.94,168.4 130.05,167.51 130.05,158.62 129.16,157.73 128.14,157.73 125.86,155.45 125.86,152.78 126.11,152.53 126.11,150.11 125.86,149.86 105.54,149.86 104.9,150.5 104.9,154.56 106.93,156.59 111.51,156.59 113.03,158.12 113.03,158.5 113.67,159.13 114.3,159.13 114.81,159.64 114.81,160.66 115.32,161.16 115.32,162.43 115.7,162.81 115.95,162.81 117.6,164.47 117.6,168.53 106.43,179.71 106.32,179.71 105.56,180.47 103.68,180.47 103,181.15 103,187.32 106.76,191.08 110.31,191.08 112.73,193.5 118.95,193.5 119.18,193.27 119.18,192.43 119.48,192.13 119.91,192.13 120.19,192.41 120.19,193.12 120.4,193.32 120.79,193.32
V_SM on TOP: 108.51,80.01 107.44,81.08 107.44,88.39 104.27,91.57 104.27,93.09 104.65,93.47 121.79,93.47 122.94,92.33 122.94,88.9 126.75,85.09 126.87,85.09 127,84.96 127,80.26 126.75,80.01 ; 16 cut-outs
V_SM on TOP: 59.16,80.72 59.04,80.84 59.04,81.67 58.85,81.86 58.85,83.67 60.38,85.19 66.37,85.19 66.65,84.91 66.65,83.57 66.37,83.29 63.2,83.29 62.84,82.93 62.84,82.37 62.69,82.22 61.16,82.22 59.66,80.72 ; 1 cut-out
V_SM on TOP: 108.56,141.16 108.05,141.66 105.38,141.66 104.88,142.17 104.24,142.17 103.99,141.92 103.73,141.92 103.61,142.04 103.61,143.7 105.41,145.5 125.3,145.5 126.16,144.63 126.16,142.93 125.27,142.04 124.71,142.04 124.45,141.78 124.46,141.76 124.46,141.28 124.38,141.21 123.24,141.21 122.27,142.17 121,142.17 120.78,141.94 120.78,141.21 120.72,141.16 119.73,141.16 118.85,142.04 118.21,142.04 117.32,141.16 116.18,141.16 116.05,141.28 116.05,141.79 115.8,142.04 114.65,142.04 113.77,141.16 113.26,141.16 112.24,142.17 111.73,142.17 111.61,142.04 111.61,141.66 111.86,141.41 111.86,141.28 111.73,141.16 111.35,141.16 110.34,142.17 109.96,142.17 109.7,141.92 109.7,141.66 109.96,141.41 109.96,141.28 109.83,141.16
V_SM on TOP: 66.42,45.72 66.17,45.97 66.17,50.72 66.29,50.85 80.72,50.85 81.23,50.34 81.23,47.12 80.59,46.48 76.33,46.48 75.56,45.72 ; 4 cut-outs
V_SM on TOP: 92.08,79.63 91.57,80.14 91.57,85.22 92.76,86.41 92.76,89.33 92.08,90.02 92.08,93.01 92.48,93.42 101.93,93.42 103.38,91.97 103.38,90.42 106.05,87.76 106.05,83.31 104.9,82.17 102.9,82.17 102.39,82.68 101.83,82.68 100.56,81.41 100.56,80.62 100.46,80.52 93.6,80.52 92.71,79.63 ; 21 cut-outs
V_SM on BOTTOM: 93.47,84.07 93.85,83.69 93.85,82.42 93.34,81.92 64.14,81.92 63.63,82.42 63.63,83.82 63.88,84.07
V_SM on BOTTOM: 80.39,52.32 80.01,51.94 80.01,46.99 80.26,46.74 90.81,46.74 95.38,51.31 95.38,62.05 94.37,63.06 91.63,63.06 89.03,60.45 89.03,53.59 87.76,52.32
V_SM on L2VCC: outline of 99 points within 91.5,57.34 127.83,145.16
V_SM_1 on TOP: 59.77,74.24 59.59,74.42 59.59,78.79 60.16,79.36 62.46,79.36 62.85,78.97 62.85,78.38 62.61,78.15 62.61,76.09 62.42,75.9 61.17,75.9 60.66,75.39 60.66,74.45 60.45,74.24 ; 4 cut-outs
V_SM_VTT on TOP: 56.9,75.18 54.05,78.03 54.05,79.81 49.78,84.07 49.78,102.87 50.93,104.01 52.7,104.01 52.96,103.76 52.96,102.11 51.94,101.09 51.94,99.57 51.56,99.19 51.56,90.17 52.45,89.28 52.45,86.36 53.61,85.2 53.61,83.48 54.66,82.42 55.42,82.42 55.7,82.14 56.46,82.14 56.58,82.03 56.58,78.65 57.05,78.18 58.62,78.18 58.88,77.93 58.88,75.51 58.55,75.18 ; 9 cut-outs
V_SM_VTT on BOTTOM: 50.8,93.47 52.2,93.47 53.21,92.46 53.21,90.55 54.29,89.47 54.29,88.58 55.18,87.69 55.18,86.49 54.36,85.66 54.36,83.57 53.47,82.68 52.7,82.68 50.42,84.96 50.42,93.09

Small or netless copper shapes (teardrops, artwork), in the pictures only: 7 on TOP, 6 on BOTTOM

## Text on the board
Ref Des/Silkscreen Top: WWW.DELL.COM | GS0521 | X3:32.768KHZ | X2:25MHZ | 1-2 | 2-3 | Normal (Default) | Clear Password | PWCLR1 | F8:2A/8V | F9:1.5A/8V | Clear COMS | X1:25MHZ | CMCLR1 | F7:1.5A/8V | F17:1.5A/8V | F5:2A/8V | F6:1.5A/8V | F18:1.5A/8V | 2 | 1 | D | C | A | B | MADE IN TAIWAN | DIH81R/General SFF MB | 48.3KZ06.011 | 12127-1 | PPID
User.18: 1 | 0
User.24: Board Accuracy Check,Aug 22 17:57:16 2013,Passed | Dummy-Static-No Shape On Layer Check,Aug 22 17:57:16 2013,Passed | Split Plane Check,Aug 22 17:57:12 2013,Passed
User.25: HEADER:EMN compare:1=show;2=show;3=show;4=show
User.28: SB3V | GND | VCC3 | AGND | V_1P05_PCH | SB5V | PWM3_LX | V_SM | MEM_LX | 1P5V_AUX | V_3P3_A | PWM2_LX | PWM1_LX | 5VDUAL_USB_R | VCC12CPU | +12V | VCC
User.31: ByImpedance:100.0@_REF_L1=("4.0/12.0(L1)")|Type="DP"|_REF_L4=("4.0/12.0(L4)")|imp="100.0" | ByImpedance:32.0@_REF_L1=("9.5(L1)")|Type="SE"|_REF_L4=("9.5(L4)")|_REF_L3=("9.0(L3)")|imp="32.0" | ByImpedance:34.0@_REF_L1=("9.0(L1)")|Type="SE"|_REF_L4=("9.0(L4)")|_REF_L3=("8.0(L3)")|imp="34.0" | ByImpedance:35.0@_REF_L1=("8.5(L1)")|Type="SE"|_REF_L4=("8.5(L4)")|_REF_L3=("7.5(L3)")|imp="35.0" | ByImpedance:37.5@_REF_L1=("7.5(L1)")|Type="SE"|_REF_L4=("7.5(L4)")|_REF_L3=("7.0(L3)")|imp="37.5" | ByImpedance:39.0@_REF_L1=("7.0(L1)")|Type="SE"|_REF_L4=("7.0(L4)")|_REF_L3=("6.5(L3)")|imp="39.0" | ByImpedance:40.0@_REF_L1=("6.5(L1)")|Type="SE"|_REF_L4=("6.5(L4)")|_REF_L3=("6.0(L3)")|imp="40.0" | ByImpedance:42.0@_REF_L1=("6.0(L1)")|Type="SE"|_REF_L4=("6.0(L4)")|_REF_L3=("5.5(L3)")|imp="42.0" | ByImpedance:45.0@_REF_L1=("5.0(L1)")|Type="SE"|_REF_L4=("5.0(L4)")|_REF_L3=("4.5(L3)")|imp="45.0" | ByImpedance:50.0@_REF_L1=("4.0(L1)")|Type="SE"|_REF_L4=("4.0(L4)")|_REF_L3=("4.0(L3)")|imp="50.0" | ByImpedance:62.0@_REF_L1=("8.5/5.0(L1)")|Type="DP"|_REF_L4=("8.5/5.0(L4)")|_REF_L3=("7.5/5.0(L3)")|imp="62.0" | ByImpedance:65.0@_REF_L1=("8.0/5.0(L1)")|Type="DP"|_REF_L4=("8.0/5.0(L4)")|_REF_L3=("7.0/5.5(L3)")|imp="65.0" | ByImpedance:70.0@_REF_L1=("7.0/5.0(L1)")|Type="DP"|_REF_L4=("7.0/5.0(L4)")|_REF_L3=("6.0/5.0(L3)")|imp="70.0" | ByImpedance:72.0@_REF_L1=("7.0/7.0(L1)")|Type="DP"|_REF_L4=("7.0/7.0(L4)")|_REF_L3=("5.5/5.0(L3)")|imp="72.0" | ByImpedance:80.0@_REF_L1=("6.0/9.0(L1)" "5.0/5.0(L1)")|Type="DP"|_REF_L4=("6.0/9.0(L4)" "5.0/5.0(L4)")|_REF_L3=("4.5/6.0(L3)")|imp="80.0" | ByImpedance:85.0@_REF_L1=("4.0/4.5(L1)" "5.0/7.0(L1)")|Type="DP"|_REF_L4=("4.0/4.5(L4)" "5.0/7.0(L4)")|_REF_L3=("4.0/6.0(L3)")|imp="85.0" | ByImpedance:90.0@_REF_L1=("4.0/6.0(L1)")|Type="DP"|_REF_L4=("4.0/6.0(L4)")|_REF_L3=("4.0/9.0(L3)")|imp="90.0" | ByImpedance:95.0@_REF_L1=("4.0/8.0(L1)")|Type="DP"|_REF_L4=("4.0/8.0(L4)")|imp="95.0" | LayerIndex:nil | Source:4-1.6-8c.xls | artWorks:("_REF_L4" "_REF_L1" "_REF_L3") | gtImpOutlineUsed:BOARD GEOMETRY/PANEL_OUTLINE
User.33: This gerber is just for your reference to find the DP impedance traces in layer L1. | DP IMPEDANCE TABLE: L1 | * - Denotes that WIDTH | is NOT used in this layer | inside board outline. | IMP(Ohm) | 62.0 | 65.0 | 70.0 | 72.0 | 80.0 | 85.0 | 90.0 | 95.0 | 100.0 | WIDTH(mils) | 8.5/5.0 | *8.0/5.0 | *7.0/5.0 | *7.0/7.0 | *6.0/9.0 | 5.0/5.0 | 4.0/4.5 | *5.0/7.0 | 4.0/6.0 | *4.0/8.0 | 4.0/12.0 | TYPE | DP
User.35: This gerber is just for your reference to find the SE impedance traces in layer L1. | SE IMPEDANCE TABLE: L1 | * - Denotes that WIDTH | is NOT used in this layer | inside board outline. | IMP(Ohm) | 32.0 | 34.0 | 35.0 | 37.5 | 39.0 | 40.0 | 42.0 | 45.0 | 50.0 | WIDTH(mils) | *9.5 | 9.0 | 8.5 | *7.5 | 7.0 | 6.5 | *6.0 | 5.0 | 4.0 | TYPE | SE
User.37: This gerber is just for your reference to find the DP impedance traces in layer L3. | DP IMPEDANCE TABLE: L3 | * - Denotes that WIDTH | is NOT used in this layer | inside board outline. | IMP(Ohm) | 62.0 | 65.0 | 70.0 | 72.0 | 80.0 | 85.0 | 90.0 | WIDTH(mils) | 7.5/5.0 | *7.0/5.5 | *6.0/5.0 | *5.5/5.0 | *4.5/6.0 | *4.0/6.0 | *4.0/9.0 | TYPE | DP
User.39: This gerber is just for your reference to find the SE impedance traces in layer L3. | SE IMPEDANCE TABLE: L3 | * - Denotes that WIDTH | is NOT used in this layer | inside board outline. | IMP(Ohm) | 32.0 | 34.0 | 35.0 | 37.5 | 39.0 | 40.0 | 42.0 | 45.0 | 50.0 | WIDTH(mils) | *9.0 | *8.0 | 7.5 | *7.0 | *6.5 | 6.0 | 5.5 | *4.5 | 4.0 | TYPE | SE
User.41: This gerber is just for your reference to find the DP impedance traces in layer L4. | DP IMPEDANCE TABLE: L4 | * - Denotes that WIDTH | is NOT used in this layer | inside board outline. | IMP(Ohm) | 62.0 | 65.0 | 70.0 | 72.0 | 80.0 | 85.0 | 90.0 | 95.0 | 100.0 | WIDTH(mils) | *8.5/5.0 | *8.0/5.0 | *7.0/5.0 | *7.0/7.0 | *6.0/9.0 | 5.0/5.0 | 4.0/4.5 | *5.0/7.0 | 4.0/6.0 | *4.0/8.0 | *4.0/12.0 | TYPE | DP
User.43: This gerber is just for your reference to find the SE impedance traces in layer L4. | SE IMPEDANCE TABLE: L4 | * - Denotes that WIDTH | is NOT used in this layer | inside board outline. | IMP(Ohm) | 32.0 | 34.0 | 35.0 | 37.5 | 39.0 | 40.0 | 42.0 | 45.0 | 50.0 | WIDTH(mils) | *9.5 | *9.0 | *8.5 | *7.5 | 7.0 | 6.5 | *6.0 | 5.0 | 4.0 | TYPE | SE
User.45: Note:Refer to DRILL layer for ELLIPSE drill direction | FIGURE | SIZE | 10.0 | 12.0 | 16.0 | 20.0 | 28.0 | 29.0 | 30.0 | 32.0 | 35.0 | 36.0 | 37.0 | 39.0 | 40.0 | 41.0 | 44.0 | 45.0 | 54.0 | 55.0 | 56.0 | 60.0 | 68.0 | 91.0 | 107.0 | 120.0 | 42.0 | 62.0 | 93.0 | 97.0 | 122.0 | 140.0 | 150.0 | 158.0 | 159.0 | 83.0x36.0 | 107.0x36.0 | 97.0x71.0 | DRILL CHART: TOP to BOTTOM | ALL UNITS ARE IN MILS | PLATED | NON-PLATED | QTY | 376 | 2691 | 708 | 48 | 18 | 680 | 14 | 19 | 16 | 63 | 52 | 15 | 3 | 4 | 24 | 2 | 6 | 20 | 1 | 7 | Model | DIH81R/General SFF MB | PCB_NO | 12127 | VER. | Layer | DRILL | L1 | L2VCC | TMASK | TPLACE | TSILK | TSMD | WSILK_T | Designer | JASON | Date | 08/22/2013 | BMASK | BPLACE | BSILK | BSMD | L3 | L4
